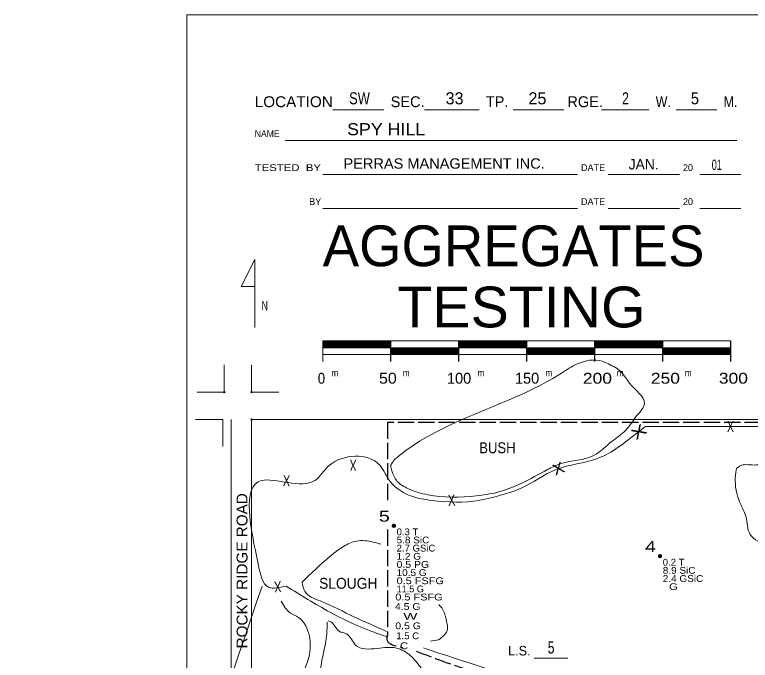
# Model space of a CAD drawing. Extents: x -577 to 499, y -450 to 700.
# Drawn here: x -577 to -35, y 225 to 700 of the extents above; entities that cross this region are included whole.
import ezdxf
from ezdxf.enums import TextEntityAlignment as Align

# ---------------------------------------------------------------- set-up
doc = ezdxf.new("R2010")
doc.units = 0
doc.header["$LTSCALE"] = 2
doc.header["$PDMODE"] = 32
doc.header["$PDSIZE"] = 1
doc.linetypes.add('LONG_DASHED', pattern=[7.5, 6, -1.5])
for name, color, linetype, lineweight in [('1', 7, 'Continuous', 13), ('2', 7, 'Continuous', 35), ('3', 7, 'Continuous', 13), ('4', 7, 'Continuous', 25)]:
    doc.layers.add(name, color=color, linetype=linetype, lineweight=lineweight)

msp = doc.modelspace()

# ---------------------------------------------------------------- linework, layer by layer
at = {"layer": '1'}
for p, q in [((-342.517, 629.973), (-305.017, 629.973)), ((-275.017, 629.973), (-235.017, 629.973)), ((-210.017, 629.973), (-172.517, 629.973)), ((-145.017, 629.973), (-110.017, 629.973)), ((-90.017, 629.973), (-60.017, 629.973)), ((-377.517, 607.473), (-45.359, 607.473)), ((-350.017, 582.473), (-162.517, 582.473)), ((-140.017, 582.473), (-87.517, 582.473)), ((-72.517, 582.473), (-42.517, 582.473)), ((-350.017, 557.473), (-162.517, 557.473)), ((-140.017, 557.473), (-87.517, 557.473)), ((-72.517, 557.473), (-42.517, 557.473)), ((-350.017, 459.973), (-350.017, 444.973)), ((-50.017, 459.973), (-350.017, 459.973)), ((-350.017, 454.973), (-50.017, 454.973)), ((-422.391, 422.339), (-422.391, 442.339)), ((-402.391, 422.339), (-402.391, 442.339)), ((-422.391, 422.339), (-442.391, 422.339)), ((-423.537, 402.339), (-443.537, 402.339)), ((-423.537, 402.339), (-423.537, 382.339)), ((-402.391, 402.339), (-402.391, -402.333)), ((-382.391, 402.339), (-402.391, 402.339)), ((-194.565, 226.553), (-169.565, 226.553))]:
    msp.add_line(p, q, dxfattribs=at)
at = {"layer": '1', "lineweight": 25}
for p, q in [((-350.017, 459.473), (-300.017, 459.473)), ((-350.017, 458.973), (-300.017, 458.973)), ((-350.017, 458.473), (-300.017, 458.473)), ((-350.017, 457.973), (-300.017, 457.973)), ((-350.017, 457.473), (-300.017, 457.473)), ((-350.017, 456.973), (-300.017, 456.973)), ((-350.017, 456.473), (-300.017, 456.473)), ((-350.017, 456.473), (-300.017, 456.473)), ((-350.017, 456.473), (-300.017, 456.473)), ((-350.017, 455.973), (-300.017, 455.973)), ((-350.017, 455.973), (-300.017, 455.973)), ((-350.017, 455.473), (-300.017, 455.473)), ((-300.017, 459.973), (-300.017, 444.973)), ((-250.017, 459.973), (-250.017, 444.973)), ((-250.017, 459.473), (-200.017, 459.473)), ((-250.017, 458.973), (-200.017, 458.973)), ((-250.017, 458.473), (-200.017, 458.473)), ((-250.017, 457.973), (-200.017, 457.973)), ((-250.017, 457.473), (-200.017, 457.473)), ((-250.017, 456.973), (-200.017, 456.973)), ((-250.017, 456.473), (-200.017, 456.473)), ((-250.017, 455.973), (-200.017, 455.973)), ((-250.017, 455.473), (-200.017, 455.473)), ((-200.017, 459.973), (-200.017, 444.973)), ((-150.017, 459.973), (-150.017, 444.973)), ((-150.017, 459.473), (-100.017, 459.473)), ((-150.017, 458.973), (-100.017, 458.973)), ((-150.017, 458.473), (-100.017, 458.473)), ((-150.017, 457.973), (-100.017, 457.973)), ((-150.017, 457.473), (-100.017, 457.473)), ((-150.017, 456.973), (-100.017, 456.973)), ((-150.017, 456.473), (-100.017, 456.473)), ((-150.017, 455.973), (-100.017, 455.973)), ((-150.017, 455.473), (-100.017, 455.473)), ((-100.017, 459.973), (-100.017, 444.973)), ((-50.017, 459.973), (-50.017, 444.973)), ((-300.017, 454.473), (-250.017, 454.473)), ((-300.017, 453.973), (-250.017, 453.973)), ((-300.017, 453.473), (-250.017, 453.473)), ((-300.017, 452.973), (-250.017, 452.973)), ((-300.017, 452.473), (-250.017, 452.473)), ((-300.017, 451.973), (-250.017, 451.973)), ((-300.017, 451.473), (-250.017, 451.473)), ((-300.017, 450.973), (-250.017, 450.973)), ((-300.017, 450.473), (-250.017, 450.473)), ((-200.017, 454.473), (-150.017, 454.473)), ((-200.017, 453.973), (-150.017, 453.973)), ((-200.017, 453.473), (-150.017, 453.473)), ((-200.017, 452.973), (-150.017, 452.973)), ((-200.017, 452.473), (-150.017, 452.473)), ((-200.017, 451.973), (-150.017, 451.973)), ((-200.017, 451.473), (-150.017, 451.473)), ((-200.017, 450.973), (-150.017, 450.973)), ((-200.017, 450.473), (-150.017, 450.473)), ((-100.017, 454.473), (-50.017, 454.473)), ((-100.017, 453.973), (-50.017, 453.973)), ((-100.017, 453.473), (-50.017, 453.473)), ((-100.017, 452.973), (-50.017, 452.973)), ((-100.017, 452.473), (-50.017, 452.473)), ((-100.017, 451.973), (-50.017, 451.973)), ((-100.017, 451.473), (-50.017, 451.473)), ((-100.017, 450.973), (-50.017, 450.973)), ((-100.017, 450.473), (-50.017, 450.473))]:
    msp.add_line(p, q, dxfattribs=at)
at = {"layer": '1'}
for points in [[(449.983, -450.027), (449.983, 399.973), (449.983, 699.973), (-450.017, 699.973), (-450.017, 49.973), (-450.017, -450.027)], [(-400.017, 469.973), (-400.017, 519.973), (-410.017, 499.973), (-400.017, 499.973)], [(-350.017, 449.973), (-50.017, 449.973), (-50.017, 459.973)], [(-402.391, 422.339), (-382.391, 422.339), (-402.391, 422.339)], [(402.281, -402.333), (402.281, 402.339), (-402.391, 402.339)]]:
    msp.add_lwpolyline(points, dxfattribs=at)
for p in [(-422.391, 422.339), (-402.391, 422.339), (-402.391, 402.339)]:
    msp.add_point(p, dxfattribs=at)
at = {"layer": '2', "linetype": 'LONG_DASHED', "lineweight": 25}
msp.add_line((-302.391, 321.405), (-302.391, 243.674), dxfattribs=at)
msp.add_lwpolyline([(302.281, 400), (-302.391, 400), (-302.391, 340.778)], dxfattribs=at)
at = {"layer": '2'}
for centre in [(-297.657, 324.104), (-101.844, 301.751)]:
    msp.add_circle(centre, 1, dxfattribs=at)
for points in [[(-297.668, 324.991), (-296.938, 324.587), (-296.786, 323.738), (-297.471, 323.21), (-298.28, 323.441), (-298.567, 324.199), (-298.32, 324.761), (-297.747, 324.929), (-297.073, 324.435), (-297.089, 323.693), (-297.606, 323.435), (-298.129, 323.604), (-298.353, 324.25), (-297.769, 324.716), (-297.331, 324.182), (-297.37, 323.699), (-297.999, 323.834), (-297.853, 324.469), (-297.561, 323.918)], [(-101.855, 302.638), (-101.125, 302.234), (-100.973, 301.386), (-101.658, 300.858), (-102.467, 301.088), (-102.754, 301.846), (-102.507, 302.408), (-101.934, 302.576), (-101.26, 302.082), (-101.276, 301.341), (-101.793, 301.082), (-102.316, 301.251), (-102.54, 301.897), (-101.956, 302.363), (-101.518, 301.829), (-101.557, 301.346), (-102.186, 301.481), (-102.04, 302.116), (-101.748, 301.565)]]:
    msp.add_spline(points, degree=3, dxfattribs=at)
at = {"layer": '2', "linetype": 'LONG_DASHED', "lineweight": 25}
for points in [[(-302.391, 243.674), (-302.82, 241.083), (-290.962, 234.421)], [(-281.328, 231.83), (-241.679, 217.766), (-223.152, 212.214), (-193.508, 201.481), (-159.789, 189.267), (-142.373, 182.975), (-121.622, 170.021), (-93.831, 153.735), (-76.045, 143.372), (-61.223, 137.08), (-27.503, 125.977), (-5.271, 120.055), (10.663, 117.094), (19.186, 115.613), (29.19, 118.204), (41.048, 124.496), (50.682, 128.937), (63.281, 140.411)]]:
    msp.add_spline(points, degree=3, dxfattribs=at)
at = {"layer": '3'}
for p, q in [((-417.391, 402.339), (-417.391, -402.333)), ((402.29, 397.182), (-112.541, 397.182)), ((-270.602, 239.238), (-264.789, 240.047))]:
    msp.add_line(p, q, dxfattribs=at)
for points in [[(-119.467, 404.582), (-113.376, 414.045), (-124.204, 428.916), (-130.294, 437.027), (-139.768, 443.11), (-144.505, 445.138), (-162.776, 443.11), (-174.28, 436.351), (-200.672, 422.157), (-294.735, 374.841), (-297.207, 372.784)], [(-300.176, 368.356), (-299.116, 364.392), (-295.132, 356.667), (-286.93, 351.284), (-272.635, 346.836), (-237.016, 346.134), (-219.674, 349.177), (-203.973, 355.263), (-184.757, 365.328), (-174.681, 369.775), (-150.778, 375.627), (-136.952, 386.394), (-127.11, 394.353), (-119.467, 404.582)], [(-376.848, 279.692), (-389.8, 278.862), (-397.525, 296.01), (-394.95, 357.313), (-355.894, 357.313), (-345.164, 368.459), (-308.253, 368.888), (-301.815, 358.599), (-285.506, 346.167), (-269.626, 342.738), (-234.861, 342.738), (-220.698, 346.167), (-203.959, 351.74), (-178.207, 365.459), (-147.735, 373.604), (-118.549, 392.467), (-112.541, 397.182)], [(-300.176, 368.356), (-298.521, 370.922), (-297.207, 372.784)], [(-45.877, 365.692), (-43.309, 367.937), (-32.557, 368.738), (-22.927, 368.738), (-19.557, 366.975), (-18.273, 364.731), (-17.952, 361.044), (-15.705, 353.51), (-8.965, 347.418), (1.306, 338.121), (12.059, 334.914), (18.479, 335.075), (22.33, 334.914), (26.824, 331.708), (31.318, 323.693), (30.997, 311.35), (26.537, 303.9)], [(-0.255, 292.406), (-0.299, 292.434), (-8.002, 299.648), (-19.718, 307.343), (-28.223, 311.831), (-34.483, 316.319), (-37.371, 322.571), (-38.174, 328.983), (-42.507, 339.724), (-46.519, 356.876), (-45.877, 365.212)], [(-365.188, 282.502), (-344.668, 301.534), (-335.874, 308.122), (-326.347, 312.514), (-314.622, 312.514), (-307.341, 310.606)], [(-365.188, 282.502), (-363.212, 275.845), (-352.002, 268.739), (-326.566, 256.897), (-303.002, 246.406)], [(-394.646, 279.734), (-399.383, -395.764), (-394.646, -399.313), (-308.58, -399.313)], [(-303.061, 242.555), (-307.447, 244.002), (-344.552, 260.474), (-376.848, 279.692)], [(-380.676, 268.556), (-373.725, 259.878), (-367.768, 256.654), (-359.824, 242.521), (-360.072, 227.892), (-363.548, 217.973), (-366.526, 209.791), (-367.023, 204.088), (-359.327, 200.865), (-348.405, 200.121), (-331.028, 200.121), (-320.602, 199.625), (-314.148, 195.906), (-301.736, 182.268), (-289.075, 168.631), (-280.635, 160.696), (-273.188, 155.241), (-265.741, 153.753), (-254.073, 154.249), (-224.036, 155.489), (-214.107, 154.993), (-213.886, 154.93)], [(-264.57, 266.038), (-261.858, 262.739), (-258.927, 253.955), (-258.194, 248.099), (-264.789, 240.047)], [(-345.922, 254.175), (-344.433, 253.679), (-337.979, 246.488), (-332.517, 244.504), (-325.815, 236.322), (-309.928, 233.842), (-295.778, 234.09), (-285.6, 228.635), (-278.153, 220.205), (-271.45, 210.535), (-269.712, 200.617), (-269.464, 183.756), (-266.734, 180.037), (-260.031, 171.358), (-256.059, 166.895), (-252.584, 165.159), (-239.675, 165.655), (-232.725, 166.647), (-223.043, 174.582), (-214.603, 181.772), (-212.865, 183.756), (-211.624, 180.78), (-215.348, 170.614), (-232.725, 166.895), (-244.64, 157.969), (-252.336, 156.977), (-269.216, 156.233), (-277.656, 163.424), (-302.232, 185.739), (-310.92, 198.633), (-325.07, 202.6), (-343.192, 201.856), (-350.391, 202.848), (-351.632, 208.055), (-351.384, 220.205), (-347.412, 241.281), (-346.667, 253.183)], [(-137.943, 184.667), (-178.266, 200.763), (-270.342, 232.334), (-275.98, 234.171)]]:
    msp.add_spline(points, degree=3, dxfattribs=at)

# ---------------------------------------------------------------- texts
at = {"layer": '1'}
for s, height, width, p in [('LOCATION', 8, 1.05, (-400.017, 631.973)), ('W.', 8, 0.85, (-105.017, 631.973)), ('M.', 8, 0.85, (-55.017, 631.973)), ('NAME', 5, 0.95, (-400.017, 609.973)), ('TESTED  BY', 5, 1.25, (-400.017, 584.973)), ('TESTING', 30, 1.05, (-295.017, 469.973)), ('N', 7, 0.7, (-395.017, 482.473)), ('0', 8, 0.9, (-353.607, 428.573)), ('m', 5, 0.9, (-343.607, 434.073)), ('50', 8, 1.1, (-308.607, 428.573)), ('m', 5, 0.9, (-291.107, 434.073)), ('m', 5, 0.9, (-236.107, 434.073)), ('m', 5, 0.9, (-186.107, 434.073)), ('200', 8, 1.2, (-158.607, 428.573)), ('m', 5, 0.9, (-133.607, 434.073)), ('250', 8, 1.2, (-108.607, 428.573)), ('m', 5, 0.9, (-83.607, 434.073)), ('300', 8, 1.2, (-58.607, 428.573))]:
    msp.add_text(s, height=height, dxfattribs=dict(at, width=width)).set_placement(p)
for s, height, width, p in [('SW', 8.89, 0.8, (-322.943, 634.038)), ('2', 8.89, 0.75, (-127.28, 634.037)), ('5', 8.89, 0.9, (-76.181, 634.038)), ('SPY HILL', 8.89, 1.1, (-303.323, 611.329)), ('PERRAS MANAGEMENT INC.', 7.62, 1.05, (-260.682, 586.728)), ('01', 7.62, 0.65, (-60.119, 585.781)), ('5', 8.89, 0.75, (-181.977, 230.084))]:
    msp.add_text(s, height=height, dxfattribs=dict(at, width=width)).set_placement(p, align=Align.CENTER)
for s, height, p in [('SEC.', 8, (-300.017, 631.973)), ('TP.', 8, (-230.017, 631.973)), ('RGE.', 8, (-170.017, 631.973)), ('DATE', 5, (-160.017, 584.973)), ('20', 5, (-85.017, 584.973)), ('BY', 5, (-360.017, 559.973)), ('DATE', 5, (-160.017, 559.973)), ('20', 5, (-85.017, 559.973)), ('AGGREGATES', 30, (-350.017, 514.973)), ('100', 8, (-258.607, 428.573)), ('150', 8, (-208.607, 428.573))]:
    msp.add_text(s, height=height, dxfattribs=at).set_placement(p)
for s, height, p in [('33', 8.89, (-253.021, 634.038)), ('25', 8.89, (-192.027, 634.038)), ('JAN.', 7.62, (-113.875, 586.148)), ('L.S.', 7, (-205.377, 228.676))]:
    msp.add_text(s, height=height, dxfattribs=at).set_placement(p, align=Align.CENTER)
at = {"layer": '2', "width": 1.35}
for s, p in [('  5', (-300.658, 327.104)), ('  4', (-104.845, 304.751))]:
    msp.add_text(s, height=8, dxfattribs=at).set_placement(p, align=Align.RIGHT)
at = {"layer": '2'}
for s, width, p in [('0.3 T      ', 1.05, (-295.657, 317.104)), ('5.8 SiC    ', 1.1, (-295.657, 311.104)), ('2.7 GSiC   ', 1.05, (-295.657, 305.104)), ('1.2 G      ', 1.1, (-295.657, 299.104)), ('0.5 PG     ', 1.15, (-295.657, 293.104)), ('0.2 T      ', 1.05, (-99.844, 294.751)), ('8.9 SiC    ', 1.1, (-99.844, 288.751)), ('10.5 G     ', 1.1, (-295.657, 287.104)), ('2.4 GSiC   ', 1.1, (-99.844, 282.751)), ('0.5 FSFG   ', 1.2, (-295.657, 281.104)), ('  G        ', 1.25, (-99.844, 276.751)), ('0.5 FSFG   ', 1.2, (-296.579, 269.127)), ('4.5 G      ', 1.15, (-296.858, 262.167)), ('  W        ', 1.65, (-296.855, 254.936)), ('0.5 G      ', 1.15, (-296.583, 247.98)), ('1.5 C      ', 1.05, (-295.874, 240.635)), ('  C        ', 1.25, (-297.812, 233.281))]:
    msp.add_text(s, height=5, dxfattribs=dict(at, width=width)).set_placement(p)
msp.add_text('11.5 G     ', height=5, dxfattribs=at).set_placement((-295.657, 275.104))
at = {"layer": '3', "width": 0.7}
msp.add_text('X', height=8, dxfattribs=at).set_placement((-50.056, 393.059), align=Align.CENTER)
at = {"layer": '3'}
for rotation, width, p in [(34.433, 1.5, (-115.214, 389.837)), (179.838, 0.7, (-327.605, 372.605)), (21.855, 1.15, (-175.161, 362.405)), (357.961, 0.75, (-376.789, 353.162)), (2.774, 0.75, (-255.001, 338.773)), (183.103, 0.75, (-383.285, 283.256))]:
    msp.add_text('X', height=8, rotation=rotation, dxfattribs=dict(at, width=width)).set_placement(p, align=Align.CENTER)
at = {"layer": '4'}
for s, width, p in [('BUSH', 0.9, (-221.479, 377.438)), ('SLOUGH', 0.95, (-331.216, 277.723))]:
    msp.add_text(s, height=8, dxfattribs=dict(at, width=width)).set_placement(p, align=Align.CENTER)
at = {"layer": '4', "width": 1.05}
msp.add_text('ROCKY RIDGE ROAD', height=8, rotation=90, dxfattribs=at).set_placement((-405.353, 290.933), align=Align.CENTER)

doc.saveas('drawing.dxf')
